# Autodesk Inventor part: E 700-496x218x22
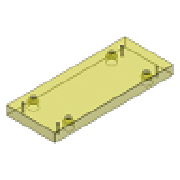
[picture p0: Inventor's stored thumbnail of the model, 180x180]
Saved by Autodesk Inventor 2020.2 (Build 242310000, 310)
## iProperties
IsCustomPart: 1
Manager: www.cadconsulting.pl
Company: Fabian Stasiak CAD Consulting
Created: 2014-02
Part Number: E 700-496x218x22
Material: S 55 C
Description: Ejector Plate
Document SubType Name: Modeling
Designer: F.Stasiak
Standard Revision: 1
Manufacturer: DME
Language: pl-PL
Size Designation: 496x218x22
Categories: <MemberInstance><Categories><Category DisplayName="Forma wtryskowa" InternalName="349578f2-f4d4-4954-8c09-8e99297a61c0" Mnemonic="MOLD"><Category DisplayName="P
Density: 7.85 g/cm^3
Appearance: Clear - Yellow
Catalog Web Link: www.expertbooks.pl
Author: F.Stasiak
Subject: Zbiór ćwiczeń. Autodesk Inventor 2020. Kurs Professional
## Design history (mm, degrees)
sketch "Sketch1"
  geometry: L1 (-109, 248)-(109, 248); L2 (109, 248)-(109, -248); L3 (109, -248)-(-109, -248); L4 (-109, -248)-(-109, 248); 5 further points
  constraints: 8 end point, 2 midpoint, 2 parallel, 1 horizontal, 1 horizontal alignment, 1 perpendicular, 1 vertical alignment
  dimensions: "d92" = 210 vertical distance of point (0, 0) point (-95, 210) (= 0.5 x S2_L); "d93" = 95 horizontal distance of point (0, 0) point (-95, 210) (= 0.5 x S2_W); "d94" = 95 horizontal distance of point (0, 0) point (-95, 233) (= 0.5 x SW_W); "d95" = 233 vertical distance of point (0, 0) point (-95, 233) (= 0.5 x SW_L); "d125" = 218 distance between parallel lines of L2 L4 (= W_); "d126" = 496 distance between parallel lines of L3 L1 (= L)
extrude "Extrusion1" new body sketch "Sketch1" distance "d20" = 22 (= H_); taper "d30" = 0 deg
hole "Hole1" sketch "Sketch1" diameter "d96" = 3.242; stored, may be unused: countersink angle "d100" = 90 deg, drill point angle "d102" = 0 deg; dims "d97" = 6, "d98" = 4, "d99" = 2, "d101" = 22 (= H_)
pattern_linear "Rectangular Pattern1" dims "d112" = 466 (computed from SW_L, Nl), "d115" = 190 (computed from SW_W, Nw)
hole "Hole2" sketch "Sketch1" diameter "d103" = 11 (= S2_d1); stored, may be unused: countersink angle "d107" = 90 deg, drill point angle "d109" = 0 deg; dims "d104" = 6, "d105" = 18 (= S2_d2), "d106" = 12 (= S2_k), "d108" = 22 (= H_)
pattern_linear "Rectangular Pattern2" dims "d118" = 420 (computed from S2_L, Nl), "d121" = 190 (computed from S2_W, Nw)
chamfer "Chamfer1" distance "d122" = 0.5; stored, may be unused: second distance "d123" = 2, angle "d124" = 45 deg
body "Solid1"
other parameters: "L" = 496 [user parameter; used in 1 equation term], "W_" = 218 [user parameter; used in 1 equation term], "H_" = 22 [user parameter; used in 3 equation terms], "S2_d1" = 11 [user parameter; used in 1 equation term], "S2_d2" = 18 [user parameter; used in 1 equation term], "S2_k" = 12 [user parameter; used in 1 equation term], "SW_L" = 466 [user parameter; used in 2 equation terms], "d127" = 54, "d128" = 134, "d129" = 22, "d130" = 0, "d131" = 0, "d132" = -180 deg, "d133" = 24, "d134" = -134, "d135" = 22, "d136" = 0, "d137" = 0, "d138" = 0, "d139" = -24, "d140" = 134, "d141" = 22, "d142" = 0, "d143" = 0, "d144" = -180 deg, "d145" = -54, "d146" = -134, "d147" = 22, "d148" = 0, "d149" = 0, "d150" = 0, "d151" = 24, "d152" = 134, "d153" = 22, "d154" = 0, "d155" = 0, "d156" = -180 deg, "d157" = 54, "d158" = -134, "d159" = 22, "d160" = 0, "d161" = 0, "d162" = 0, "d163" = -54, "d164" = 134, "d165" = 22, "d166" = 0, "d167" = 0, "d168" = -180 deg, "d169" = -24, "d170" = -134, "d171" = 22, "d172" = 0, "d173" = 0, "d174" = 0, "d175" = 54, "d176" = 103.5, "d177" = 22, "d178" = 0, "d179" = 0, "d180" = -180 deg, "d181" = 24, "d182" = -103.5, "d183" = 22, "d184" = 0, "d185" = 0, "d186" = 0, "d187" = -24, "d188" = 103.5, "d189" = 22, "d190" = 0, "d191" = 0, "d192" = -180 deg, "d193" = -54, "d194" = -103.5, "d195" = 22, "d196" = 0, "d197" = 0, "d198" = 0, "d199" = 24, "d200" = 103.5, "d201" = 22, "d202" = 0, "d203" = 0, "d204" = -180 deg, "d205" = 54, "d206" = -103.5, "d207" = 22, "d208" = 0, "d209" = 0, "d210" = 0, "d211" = -54, "d212" = 103.5, "d213" = 22, "d214" = 0, "d215" = 0, "d216" = -180 deg, "d217" = -24, "d218" = -103.5, "d219" = 22, "d220" = 0, "d221" = 0, "d222" = 0, "d223" = 47, "d224" = 71.2, "d225" = 22, "d226" = 0, "d227" = 0, "d228" = -180 deg, "d229" = 31, "d230" = -71.2, "d231" = 22, "d232" = 0, "d233" = 0, "d234" = 0, "d235" = -31, "d236" = 71.2, "d237" = 22, "d238" = 0, "d239" = 0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
